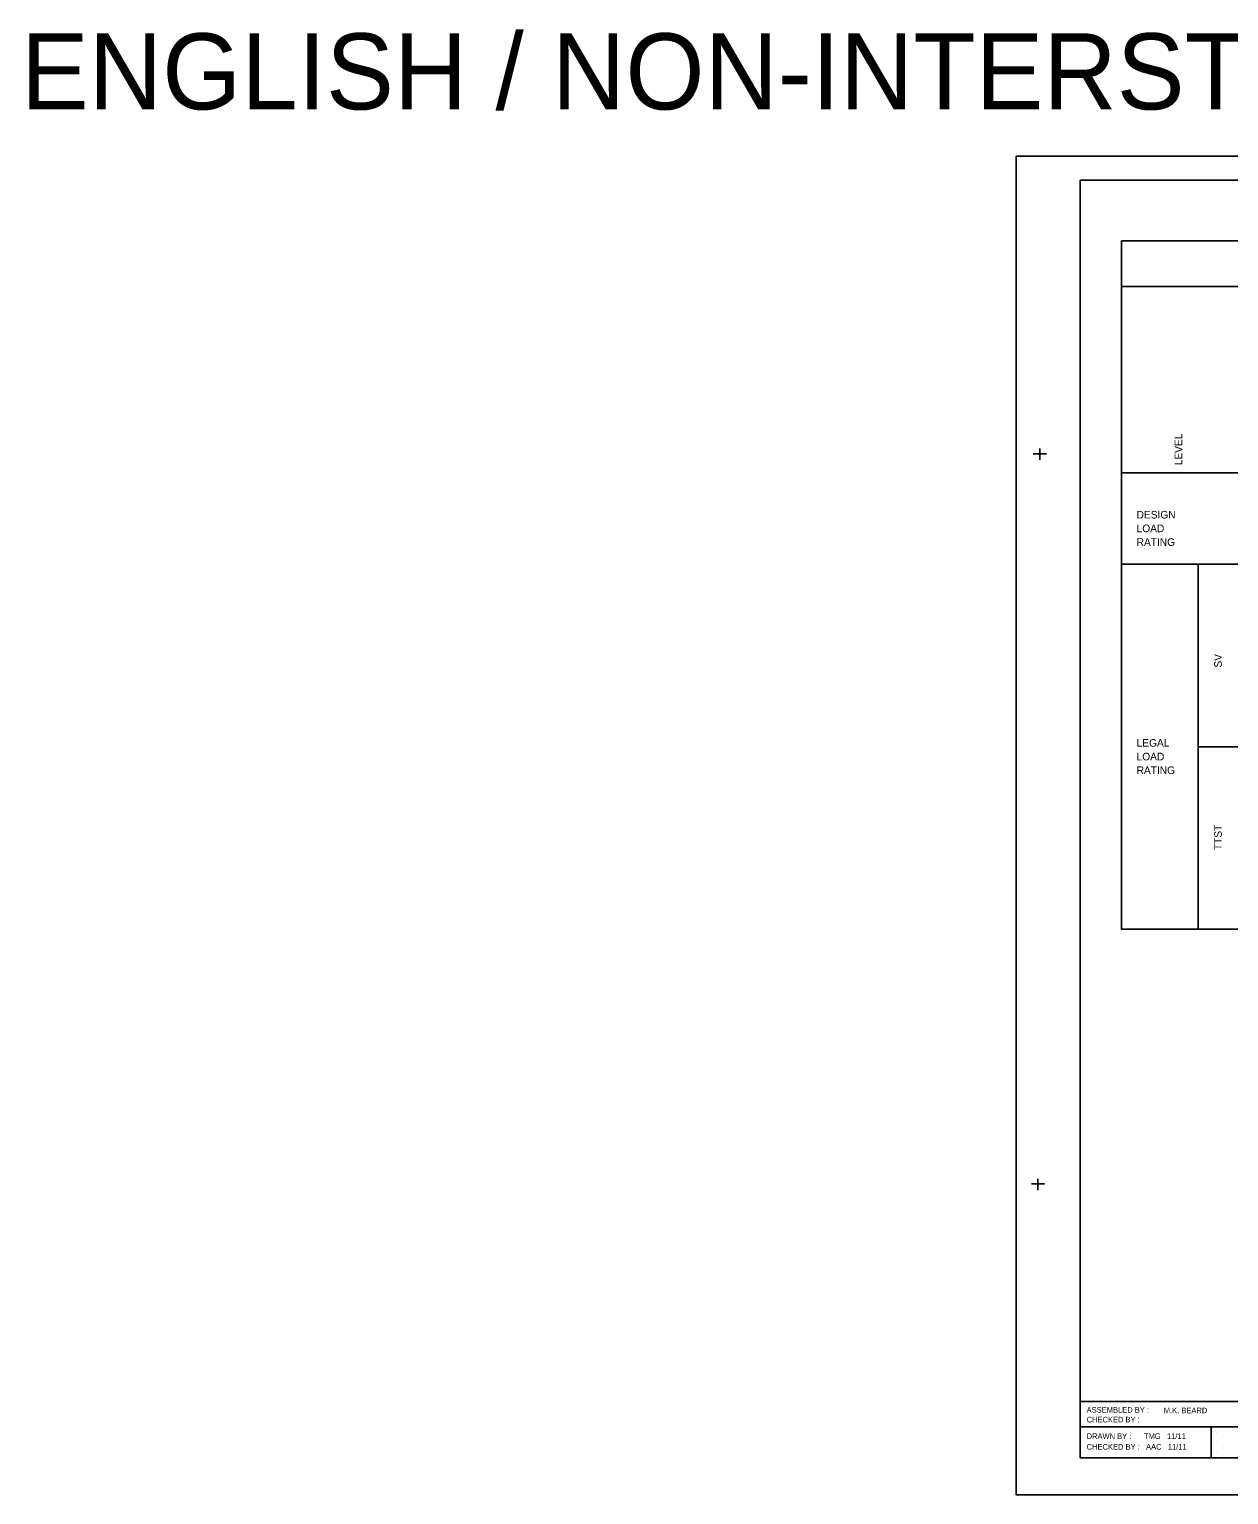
# Model space of a CAD drawing. Extents: x -190 to 360, y 729 to 1065.
# Drawn here: x -189.6 to 7.6, y 729.5 to 970.3 of the extents above; entities that cross this region are included whole.
import ezdxf

# ---------------------------------------------------------------- set-up
doc = ezdxf.new("R2010")
doc.units = 0
for name, color, linetype in [('Bill of Material Border Lines', 7, 'Continuous'), ('Bill of Material Lines', 7, 'Continuous'), ('Plan Sheet', 7, 'Continuous'), ('Plan Sheet CELL', 7, 'Continuous'), ('Plot Shape CELL', 7, 'Continuous'), ('Text', 7, 'Continuous'), ('User Information Notes', 7, 'Continuous'), ('User Information Notes CELL', 7, 'Continuous')]:
    doc.layers.add(name, color=color, linetype=linetype)

msp = doc.modelspace()

# ---------------------------------------------------------------- linework, layer by layer
at = {"layer": 'Bill of Material Border Lines'}
msp.add_lwpolyline([(-9.99, 935.55), (226.51, 935.55), (226.51, 822.42), (-9.99, 822.42), (-9.99, 935.55)], dxfattribs=at)
at = {"layer": 'Bill of Material Lines'}
for p, q in [((-9.99, 928.05), (226.51, 928.05)), ((-9.99, 897.42), (226.51, 897.42)), ((-9.99, 882.42), (226.51, 882.42)), ((2.64, 882.42), (2.64, 822.42)), ((2.64, 852.42), (226.51, 852.42))]:
    msp.add_line(p, q, dxfattribs=at)
at = {"layer": 'Plan Sheet'}
for p, q in [((-16.76, 744.81), (24.88, 744.81)), ((24.88, 740.63), (-16.76, 740.63)), ((4.79, 735.55), (4.79, 740.63))]:
    msp.add_line(p, q, dxfattribs=at)
at = {"layer": 'Plan Sheet CELL'}
for p, q in [((-27.3, 949.49), (-27.3, 949.49)), ((-16.76, 945.55), (303.24, 945.55)), ((-16.76, 735.55), (-16.76, 945.55)), ((-23.42, 899.54), (-23.42, 901.44)), ((-24.49, 900.55), (-22.29, 900.55)), ((-24.75, 780.55), (-22.65, 780.55)), ((-23.73, 779.56), (-23.73, 781.37)), ((-16.76, 735.55), (303.24, 735.55)), ((-27.3, 729.49), (-27.3, 729.49))]:
    msp.add_line(p, q, dxfattribs=at)
at = {"layer": 'Plot Shape CELL'}
msp.add_lwpolyline([(-27.3, 949.49), (303.33, 949.49), (303.33, 729.49), (-27.3, 729.49)], close=True, dxfattribs=at)
at = {"layer": 'User Information Notes'}
for p, q in [((5.7, 739.73), (5.7, 739.73)), ((5.7, 738.18), (5.7, 738.18)), ((5.7, 736.62), (5.7, 736.62))]:
    msp.add_line(p, q, dxfattribs=at)
at = {"layer": 'User Information Notes CELL'}
for p, q in [((-27.3, 949.87), (-27.3, 949.87)), ((-16.76, 945.55), (-16.76, 945.55))]:
    msp.add_line(p, q, dxfattribs=at)

# ---------------------------------------------------------------- texts
at = {"layer": 'Plan Sheet'}
for s, height, p in [('ASSEMBLED BY :', 0.9255, (-15.71, 742.96)), ('CHECKED BY :', 0.9255, (-15.71, 741.36)), ('DRAWN BY :      TMG   11/11', 0.9258, (-15.71, 738.64)), ('CHECKED BY :   AAC   11/11  ', 0.9258, (-15.71, 736.89))]:
    msp.add_text(s, height=height, dxfattribs=at).set_placement(p)
at = {"layer": 'Text'}
for s, p in [('LEVEL', (0.01, 898.67)), ('SV', (6.51, 865.42)), ('TTST', (6.51, 835.42))]:
    msp.add_text(s, height=1.25, rotation=90, dxfattribs=at).set_placement(p)
for s, height, p in [('DESIGN', 1.25, (-7.49, 889.92)), ('LOAD', 1.25, (-7.49, 887.67)), ('RATING', 1.25, (-7.49, 885.42)), ('LEGAL', 1.25, (-7.49, 852.42)), ('LOAD', 1.25, (-7.49, 850.17)), ('RATING', 1.25, (-7.49, 847.92)), ('M.K. BEARD', 0.925, (-3.02, 742.88))]:
    msp.add_text(s, height=height, dxfattribs=at).set_placement(p)
at = {"layer": 'User Information Notes'}
msp.add_text('ENGLISH / NON-INTERSTATE / PRESTRESSED CONCRETE GIRDERS ', height=12.5, dxfattribs=at).set_placement((-190.93, 957.15))

doc.saveas('drawing.dxf')
